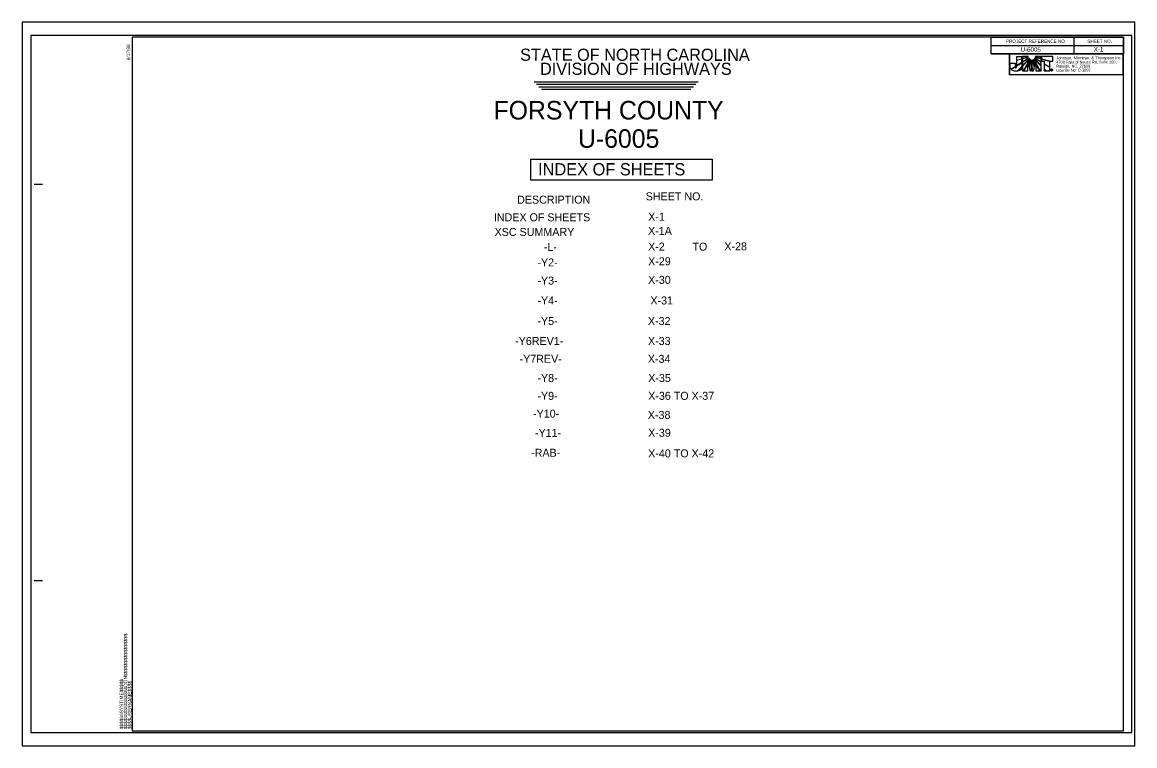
# Model space of a CAD drawing. Extents: x 2221 to 2389, y -3371 to -3261.
import ezdxf

# ---------------------------------------------------------------- set-up
doc = ezdxf.new("R2010")
doc.units = 0
for name, color, linetype in [('Default', 7, 'Continuous'), ('Old_Level_12', 7, 'Continuous'), ('Old_Level_40', 7, 'Continuous'), ('Old_Level_44', 7, 'Continuous'), ('Prop PHM Black Shape', 7, 'Continuous'), ('Sheet Block Title CELL', 7, 'Continuous'), ('Sheet Data Field CELL', 7, 'Continuous'), ('Sheet Plan CELL', 7, 'Continuous'), ('Sheet Plot Border Inside CELL', 7, 'Continuous'), ('Sheet Plot Border Outside CELL', 7, 'Continuous')]:
    doc.layers.add(name, color=color, linetype=linetype)

msp = doc.modelspace()

# ---------------------------------------------------------------- linework, layer by layer
at = {"layer": 'Default'}
for p, q in [((2372.01, -3266.51), (2371.2, -3266.51)), ((2371.2, -3266.51), (2371.21, -3267.04)), ((2371.21, -3267.04), (2372.01, -3266.82)), ((2372.01, -3266.87), (2371.21, -3267.1)), ((2371.21, -3267.1), (2371.21, -3267.85)), ((2371.21, -3267.85), (2372.01, -3267.34)), ((2372.01, -3266.82), (2372.01, -3266.51)), ((2372.01, -3267.34), (2372.01, -3266.87)), ((2373, -3266.5), (2372.09, -3266.5)), ((2372.09, -3266.5), (2372.09, -3266.79)), ((2372.09, -3266.79), (2372.77, -3266.6)), ((2372.77, -3266.66), (2372.09, -3266.85)), ((2372.09, -3266.85), (2372.09, -3267.29)), ((2372.09, -3267.29), (2372.7, -3266.9)), ((2372.79, -3266.91), (2372.09, -3267.36)), ((2372.09, -3267.36), (2372.1, -3267.86)), ((2372.1, -3267.86), (2372.94, -3266.97)), ((2372.98, -3267.02), (2372.1, -3267.94)), ((2372.23, -3268.67), (2372.89, -3267.48)), ((2372.89, -3267.6), (2372.29, -3268.67)), ((2372.7, -3266.9), (2373.03, -3266.63)), ((2372.77, -3266.6), (2373, -3266.5)), ((2373.03, -3266.63), (2372.77, -3266.66)), ((2373.1, -3266.76), (2372.79, -3266.91)), ((2372.89, -3267.48), (2372.88, -3267.27)), ((2372.88, -3267.27), (2372.92, -3267.42)), ((2372.89, -3268.67), (2372.89, -3267.6)), ((2372.92, -3267.42), (2373.09, -3267.11)), ((2372.94, -3266.97), (2373.1, -3266.76)), ((2373.15, -3267.13), (2372.95, -3267.49)), ((2372.95, -3267.49), (2373.08, -3267.98)), ((2373.19, -3266.85), (2372.98, -3267.02)), ((2373.08, -3267.98), (2373.28, -3267.17)), ((2373.09, -3267.11), (2373.19, -3266.85)), ((2373.33, -3267.22), (2373.1, -3268.09)), ((2373.31, -3266.92), (2373.15, -3267.13)), ((2373.28, -3267.17), (2373.31, -3266.92)), ((2373.44, -3266.96), (2373.33, -3267.22)), ((2373.47, -3267.59), (2373.44, -3266.96)), ((2373.48, -3268.67), (2373.47, -3267.59)), ((2373.57, -3266.96), (2373.53, -3267.59)), ((2373.53, -3267.59), (2373.54, -3268.67)), ((2373.68, -3267.22), (2373.57, -3266.96)), ((2373.91, -3268.1), (2373.68, -3267.22)), ((2373.7, -3266.92), (2373.73, -3267.18)), ((2373.86, -3267.13), (2373.7, -3266.92)), ((2373.73, -3267.18), (2373.94, -3267.99)), ((2373.81, -3266.85), (2373.91, -3267.11)), ((2374.03, -3267.01), (2373.81, -3266.85)), ((2374.07, -3267.5), (2373.86, -3267.13)), ((2373.91, -3266.75), (2374.06, -3266.97)), ((2374.22, -3266.91), (2373.91, -3266.75)), ((2373.91, -3267.11), (2374.09, -3267.43)), ((2373.94, -3267.99), (2374.07, -3267.5)), ((2373.98, -3266.63), (2374.32, -3266.9)), ((2374.23, -3266.66), (2373.98, -3266.63)), ((2374.91, -3266.5), (2374.02, -3266.49)), ((2374.02, -3266.49), (2374.25, -3266.6)), ((2374.91, -3267.94), (2374.03, -3267.01)), ((2374.06, -3266.97), (2374.91, -3267.86)), ((2374.09, -3267.43), (2374.13, -3267.27)), ((2374.13, -3267.27), (2374.13, -3267.5)), ((2374.13, -3267.5), (2374.77, -3268.67)), ((2374.71, -3268.66), (2374.13, -3267.62)), ((2374.13, -3267.62), (2374.13, -3268.66)), ((2374.91, -3267.34), (2374.22, -3266.91)), ((2374.92, -3266.85), (2374.23, -3266.66)), ((2374.25, -3266.6), (2374.92, -3266.79)), ((2374.32, -3266.9), (2374.91, -3267.27)), ((2374.92, -3266.79), (2374.91, -3266.5)), ((2374.91, -3267.27), (2374.92, -3266.85)), ((2374.91, -3267.86), (2374.91, -3267.34)), ((2376.67, -3266.49), (2374.98, -3266.49)), ((2374.98, -3266.49), (2374.98, -3266.8)), ((2374.98, -3266.8), (2374.98, -3266.81)), ((2374.98, -3266.81), (2376.31, -3267.18)), ((2374.98, -3266.86), (2374.98, -3266.86)), ((2374.98, -3266.86), (2374.98, -3267.19)), ((2376.23, -3267.21), (2374.98, -3266.86)), ((2374.98, -3267.19), (2375.39, -3267.19)), ((2375.39, -3267.19), (2375.39, -3267.57)), ((2375.39, -3267.57), (2376.23, -3268.1)), ((2375.39, -3267.64), (2375.4, -3268.36)), ((2376.23, -3268.16), (2375.39, -3267.64)), ((2376.23, -3268.1), (2376.23, -3267.21)), ((2376.31, -3267.18), (2376.67, -3267.18)), ((2376.67, -3267.18), (2376.67, -3266.49)), ((2372.1, -3267.94), (2372.1, -3268.67)), ((2372.1, -3268.67), (2372.23, -3268.67)), ((2372.29, -3268.67), (2372.89, -3268.67)), ((2373.1, -3268.09), (2373.26, -3268.67)), ((2373.26, -3268.67), (2373.48, -3268.67)), ((2373.54, -3268.67), (2373.76, -3268.66)), ((2373.76, -3268.66), (2373.91, -3268.1)), ((2374.13, -3268.66), (2374.71, -3268.66)), ((2374.77, -3268.67), (2374.92, -3268.66)), ((2374.92, -3268.66), (2374.91, -3267.94)), ((2375.4, -3268.36), (2375.68, -3268.66)), ((2375.61, -3268.66), (2375.4, -3268.44)), ((2375.4, -3268.44), (2375.4, -3268.66)), ((2375.4, -3268.66), (2375.61, -3268.66)), ((2375.68, -3268.66), (2376.23, -3268.66)), ((2376.23, -3268.66), (2376.23, -3268.16)), ((2376.44, -3268.58), (2376.44, -3268.46)), ((2376.44, -3268.46), (2376.49, -3268.46)), ((2376.47, -3268.58), (2376.44, -3268.58)), ((2376.49, -3268.48), (2376.47, -3268.48)), ((2376.47, -3268.48), (2376.47, -3268.51)), ((2376.47, -3268.51), (2376.49, -3268.51)), ((2376.49, -3268.54), (2376.47, -3268.54)), ((2376.47, -3268.54), (2376.47, -3268.58)), ((2376.49, -3268.39), (2376.49, -3268.41)), ((2376.49, -3268.41), (2376.49, -3268.39)), ((2376.49, -3268.46), (2376.49, -3268.48)), ((2376.49, -3268.48), (2376.49, -3268.46)), ((2376.49, -3268.46), (2376.5, -3268.46)), ((2376.5, -3268.48), (2376.49, -3268.48)), ((2376.49, -3268.51), (2376.49, -3268.54)), ((2376.49, -3268.54), (2376.49, -3268.51)), ((2376.49, -3268.51), (2376.49, -3268.51)), ((2376.49, -3268.54), (2376.49, -3268.54)), ((2376.49, -3268.63), (2376.49, -3268.66)), ((2376.49, -3268.66), (2376.49, -3268.63)), ((2376.49, -3268.63), (2376.49, -3268.63)), ((2376.49, -3268.66), (2376.49, -3268.66))]:
    msp.add_line(p, q, dxfattribs=at)
for points in [[(2370.12, -3269.23), (2387.31, -3269.19), (2387.31, -3266.09), (2370.11, -3266.13)], [(2372.1, -3268.67), (2372.1, -3267.94), (2372.98, -3267.02), (2373.19, -3266.85), (2373.12, -3267.06), (2372.92, -3267.42), (2372.88, -3267.27), (2372.89, -3267.48), (2372.23, -3268.67)], [(2374.02, -3266.49), (2374.91, -3266.5), (2374.92, -3266.79), (2374.25, -3266.6)], [(2297.67, -3282.01), (2325.14, -3282.01), (2325.14, -3285.21), (2297.67, -3285.21)]]:
    msp.add_lwpolyline(points, close=True, dxfattribs=at)
for points in [[(2371.21, -3267.04), (2372.01, -3266.82), (2372.01, -3266.51), (2371.2, -3266.51), (2371.21, -3267.04)], [(2371.21, -3267.85), (2372.01, -3267.34), (2372.01, -3266.87), (2371.21, -3267.1), (2371.21, -3267.85)], [(2372.77, -3266.6), (2373, -3266.5), (2372.09, -3266.5), (2372.09, -3266.79), (2372.77, -3266.6)], [(2372.09, -3266.85), (2372.09, -3267.29), (2372.7, -3266.9), (2373.03, -3266.63), (2372.77, -3266.66), (2372.09, -3266.85)], [(2372.09, -3267.36), (2372.1, -3267.86), (2372.94, -3266.97), (2373.1, -3266.76), (2372.79, -3266.91), (2372.09, -3267.36)], [(2373.19, -3266.85), (2372.98, -3267.02), (2372.1, -3267.94), (2372.1, -3268.67), (2372.23, -3268.67), (2372.89, -3267.48), (2372.88, -3267.27), (2372.92, -3267.42), (2373.09, -3267.11), (2373.19, -3266.85)], [(2372.29, -3268.67), (2372.89, -3268.67), (2372.89, -3267.6), (2372.29, -3268.67)], [(2373.31, -3266.92), (2373.15, -3267.13), (2372.95, -3267.49), (2373.08, -3267.98), (2373.28, -3267.17), (2373.31, -3266.92)], [(2373.33, -3267.22), (2373.1, -3268.09), (2373.26, -3268.67), (2373.48, -3268.67), (2373.47, -3267.59), (2373.44, -3266.96), (2373.33, -3267.22)], [(2373.57, -3266.96), (2373.53, -3267.59), (2373.54, -3268.67), (2373.76, -3268.66), (2373.91, -3268.1), (2373.68, -3267.22), (2373.57, -3266.96)], [(2373.7, -3266.92), (2373.73, -3267.18), (2373.94, -3267.99), (2374.07, -3267.5), (2373.86, -3267.13), (2373.7, -3266.92)], [(2373.81, -3266.85), (2373.91, -3267.11), (2374.09, -3267.43), (2374.13, -3267.27), (2374.13, -3267.5), (2374.77, -3268.67), (2374.92, -3268.66), (2374.91, -3267.94), (2374.03, -3267.01), (2373.81, -3266.85)], [(2373.91, -3266.75), (2374.06, -3266.97), (2374.91, -3267.86), (2374.91, -3267.34), (2374.22, -3266.91), (2373.91, -3266.75)], [(2373.98, -3266.63), (2374.32, -3266.9), (2374.91, -3267.27), (2374.92, -3266.85), (2374.23, -3266.66), (2373.98, -3266.63)], [(2374.25, -3266.6), (2374.92, -3266.79), (2374.91, -3266.5), (2374.02, -3266.49), (2374.25, -3266.6)], [(2374.13, -3268.66), (2374.71, -3268.66), (2374.13, -3267.62), (2374.13, -3268.66)], [(2376.67, -3266.49), (2374.98, -3266.49), (2374.98, -3266.8), (2374.98, -3266.81), (2376.31, -3267.18), (2376.67, -3267.18), (2376.67, -3266.49)], [(2374.98, -3266.86), (2374.98, -3266.86), (2374.98, -3267.19), (2375.39, -3267.19), (2375.39, -3267.57), (2376.23, -3268.1), (2376.23, -3267.21), (2374.98, -3266.86)], [(2375.39, -3267.64), (2375.4, -3268.36), (2375.68, -3268.66), (2376.23, -3268.66), (2376.23, -3268.16), (2375.39, -3267.64), (2375.39, -3267.64)], [(2375.4, -3268.66), (2375.4, -3268.66), (2375.61, -3268.66), (2375.4, -3268.44), (2375.4, -3268.66)], [(2376.55, -3268.55), (2376.55, -3268.56), (2376.55, -3268.57), (2376.55, -3268.57), (2376.55, -3268.58), (2376.52, -3268.58)]]:
    msp.add_lwpolyline(points, dxfattribs=at)
for points, degree in [([(2370.98, -3267.51), (2370.98, -3267.51), (2370.23, -3267.51), (2370.23, -3267.51), (2370.23, -3267.51), (2370.23, -3267.98), (2370.23, -3267.98), (2370.23, -3267.98), (2370.23, -3268.03), (2370.23, -3268.03), (2370.23, -3268.17), (2370.28, -3268.29), (2370.37, -3268.38), (2370.37, -3268.38), (2370.98, -3268.01), (2370.98, -3268), (2370.98, -3268), (2370.98, -3267.51), (2370.98, -3267.51)], 3), ([(2371.09, -3268.18), (2371.05, -3268.18), (2371, -3268.15), (2370.99, -3268.06), (2370.99, -3268.06), (2370.41, -3268.42), (2370.41, -3268.42), (2370.59, -3268.61), (2370.87, -3268.72), (2371.11, -3268.72), (2371.18, -3268.72), (2371.22, -3268.71), (2371.29, -3268.7), (2371.29, -3268.7), (2372.01, -3267.95), (2372.01, -3267.95), (2372.01, -3267.95), (2372.01, -3267.41), (2372.01, -3267.41), (2372.01, -3267.41), (2371.21, -3267.92), (2371.21, -3267.92), (2371.21, -3268.12), (2371.16, -3268.18), (2371.09, -3268.18)], 3), ([(2371.09, -3268.18), (2371.05, -3268.18), (2371, -3268.15), (2370.99, -3268.06), (2370.99, -3268.06), (2370.41, -3268.42), (2370.41, -3268.42), (2370.59, -3268.61), (2370.87, -3268.72), (2371.11, -3268.72), (2371.18, -3268.72), (2371.22, -3268.71), (2371.29, -3268.7), (2371.29, -3268.7), (2372.01, -3267.95), (2372.01, -3267.95), (2372.01, -3267.95), (2372.01, -3267.41), (2372.01, -3267.41), (2372.01, -3267.41), (2371.21, -3267.92), (2371.21, -3267.92), (2371.21, -3268.12), (2371.16, -3268.18), (2371.09, -3268.18)], 3), ([(2372.01, -3268.03), (2372.01, -3268.03), (2371.39, -3268.68), (2371.39, -3268.68), (2371.7, -3268.61), (2372, -3268.4), (2372.01, -3268.03)], 3), ([(2376.49, -3268.66), (2376.46, -3268.66), (2376.42, -3268.65), (2376.4, -3268.62), (2376.37, -3268.59), (2376.36, -3268.56), (2376.36, -3268.52), (2376.36, -3268.48), (2376.37, -3268.45), (2376.4, -3268.43), (2376.42, -3268.4), (2376.45, -3268.39), (2376.49, -3268.39)], 3), ([(2376.49, -3268.41), (2376.46, -3268.41), (2376.44, -3268.42), (2376.41, -3268.44), (2376.39, -3268.47), (2376.38, -3268.49), (2376.38, -3268.52), (2376.38, -3268.55), (2376.39, -3268.58), (2376.42, -3268.6), (2376.44, -3268.62), (2376.46, -3268.63), (2376.49, -3268.63)], 3), ([(2376.49, -3268.39), (2376.53, -3268.39), (2376.56, -3268.4), (2376.59, -3268.43), (2376.62, -3268.45), (2376.63, -3268.48), (2376.63, -3268.52)], 3), ([(2376.49, -3268.63), (2376.52, -3268.63), (2376.55, -3268.62), (2376.57, -3268.6), (2376.59, -3268.58), (2376.6, -3268.55), (2376.6, -3268.52), (2376.6, -3268.49), (2376.59, -3268.46), (2376.57, -3268.44), (2376.55, -3268.42), (2376.52, -3268.41), (2376.49, -3268.41)], 3), ([(2376.49, -3268.51), (2376.51, -3268.51), (2376.52, -3268.51), (2376.52, -3268.5), (2376.52, -3268.49), (2376.51, -3268.48), (2376.5, -3268.48)], 3), ([(2376.63, -3268.52), (2376.63, -3268.56), (2376.62, -3268.59), (2376.59, -3268.62), (2376.56, -3268.64), (2376.53, -3268.66), (2376.49, -3268.66)], 3), ([(2376.51, -3268.54), (2376.51, -3268.54), (2376.5, -3268.54), (2376.49, -3268.54)], 2), ([(2376.5, -3268.46), (2376.53, -3268.46), (2376.55, -3268.47), (2376.55, -3268.5), (2376.55, -3268.51), (2376.54, -3268.52), (2376.53, -3268.52)], 3), ([(2376.52, -3268.58), (2376.52, -3268.58), (2376.52, -3268.57), (2376.52, -3268.56), (2376.52, -3268.55), (2376.52, -3268.54), (2376.51, -3268.54)], 3), ([(2376.53, -3268.52), (2376.54, -3268.53), (2376.54, -3268.54), (2376.55, -3268.55)], 2)]:
    msp.add_open_spline(points, degree=degree, dxfattribs=at)
at = {"layer": 'Old_Level_12'}
for p, q in [((2298.2, -3270.29), (2323.04, -3270.3)), ((2298.2, -3270.3), (2323.04, -3270.3)), ((2298.55, -3270.68), (2322.65, -3270.68)), ((2298.93, -3271.05), (2322.29, -3271.05)), ((2299.3, -3271.42), (2321.9, -3271.42))]:
    msp.add_line(p, q, dxfattribs=at)
at = {"layer": 'Prop PHM Black Shape'}
msp.add_lwpolyline([(2370.11, -3266.13), (2387.31, -3266.09), (2387.31, -3269.19), (2370.12, -3269.23)], close=True, dxfattribs=at)
at = {"layer": 'Sheet Block Title CELL'}
for p, q in [((2379.88, -3263.55), (2379.88, -3266.05)), ((2367.38, -3264.8), (2387.38, -3264.8)), ((2367.38, -3266.05), (2387.38, -3266.05))]:
    msp.add_line(p, q, dxfattribs=at)
msp.add_lwpolyline([(2367.38, -3263.54), (2387.38, -3263.54), (2387.38, -3266.05), (2367.38, -3266.05)], close=True, dxfattribs=at)
at = {"layer": 'Sheet Plan CELL'}
for p, q in [((2237.38, -3263.54), (2237.38, -3263.54)), ((2222.53, -3285.79), (2223.78, -3285.79)), ((2222.53, -3345.8), (2223.78, -3345.8)), ((2237.38, -3368.55), (2237.38, -3368.55))]:
    msp.add_line(p, q, dxfattribs=at)
msp.add_lwpolyline([(2387.38, -3263.54), (2237.38, -3263.54), (2237.38, -3368.55), (2387.38, -3368.55)], close=True, dxfattribs=at)
at = {"layer": 'Sheet Plot Border Inside CELL'}
msp.add_lwpolyline([(2222.03, -3368.8), (2388.63, -3368.8), (2388.63, -3263.29), (2222.03, -3263.29)], close=True, dxfattribs=at)
at = {"layer": 'Sheet Plot Border Outside CELL'}
msp.add_lwpolyline([(2220.73, -3370.8), (2389.08, -3370.8), (2389.08, -3261.29), (2220.73, -3261.29)], close=True, dxfattribs=at)

# ---------------------------------------------------------------- texts
at = {"layer": 'Default'}
for s, height, rotation, p in [('Johnson, Mirmiran, & Thompson Inc.', 0.4392, 0.1414, (2377.2, -3266.91)), ('4700 Falls of Neuse Rd, Suite 100, ', 0.4267, 0.1414, (2377.2, -3267.55)), ('Raleigh, NC, 27609', 0.4267, 0.1414, (2377.2, -3268.16)), ('License No: C-3097', 0.4267, 0.1414, (2377.2, -3268.77)), ('INDEX OF SHEETS', 1.8509, 359.992, (2298.79, -3284.47)), ('DESCRIPTION', 1.2112, 359.992, (2295.62, -3288.75)), ('SHEET NO.', 1.211, 359.992, (2315.08, -3288.25))]:
    msp.add_text(s, height=height, rotation=rotation, dxfattribs=at).set_placement(p)
for s, height, p in [('INDEX OF SHEETS ', 1.2112, (2292.1, -3291.42)), ('X-1', 1.211, (2315.45, -3291.34)), ('XSC SUMMARY', 1.2112, (2292.21, -3293.64)), ('X-1A', 1.211, (2315.43, -3293.47)), ('X-2', 1.211, (2315.44, -3295.85)), ('TO', 1.211, (2322.15, -3295.86)), ('X-28', 1.211, (2326.98, -3295.82)), ('-L-', 1.211, (2299.67, -3295.92)), ('-Y2-', 1.211, (2298.69, -3298.25)), ('X-29', 1.211, (2315.44, -3298.08)), ('X-30', 1.211, (2315.44, -3300.89)), ('-Y3-', 1.211, (2298.69, -3301)), ('-Y4-', 1.211, (2298.69, -3304.01)), ('X-31', 1.211, (2315.79, -3304.01)), ('-Y5-', 1.211, (2298.69, -3307.12)), ('X-32', 1.211, (2315.41, -3307.12)), ('-Y6REV1-', 1.211, (2295.32, -3310.14)), ('X-33', 1.211, (2315.42, -3310.14)), ('-Y7REV-', 1.211, (2295.99, -3312.84)), ('X-34', 1.211, (2315.4, -3312.84)), ('-Y8-', 1.211, (2298.69, -3315.74)), ('X-35', 1.211, (2315.46, -3315.74)), ('-Y9-', 1.211, (2298.69, -3318.44)), ('X-36 TO X-37', 1.2112, (2315.45, -3318.44)), ('-Y10-', 1.211, (2298.03, -3321.14)), ('X-38', 1.211, (2315.4, -3321.33)), ('-Y11-', 1.211, (2298.32, -3324.05)), ('X-39', 1.211, (2315.45, -3324.03)), ('-RAB-', 1.211, (2297.74, -3327.06)), ('X-40 TO X-42', 1.2112, (2315.45, -3327.15))]:
    msp.add_text(s, height=height, dxfattribs=at).set_placement(p)
at = {"layer": 'Old_Level_40'}
for s, height, p in [('FORSYTH COUNTY', 2.8069, (2292.05, -3276.01)), ('U-6005', 2.807, (2304.83, -3280.3))]:
    msp.add_text(s, height=height, rotation=359.9982, dxfattribs=at).set_placement(p)
at = {"layer": 'Old_Level_44'}
for s, p in [('STATE OF NORTH CAROLINA', (2296.07, -3267.13)), ('DIVISION OF HIGHWAYS', (2299.08, -3269.26))]:
    msp.add_text(s, height=1.8416, rotation=359.9915, dxfattribs=at).set_placement(p)
at = {"layer": 'Sheet Block Title CELL'}
for s, p in [('PROJECT REFERENCE NO.', (2369.6, -3264.41)), ('SHEET NO.', (2381.91, -3264.42))]:
    msp.add_text(s, height=0.5, dxfattribs=at).set_placement(p)
at = {"layer": 'Sheet Data Field CELL'}
for s, p in [('U-6005', (2371.81, -3265.76)), ('X-1', (2382.88, -3265.73))]:
    msp.add_text(s, height=0.675, dxfattribs=at).set_placement(p)
at = {"layer": 'Sheet Plan CELL'}
for s, p in [('8/17/99', (2237.06, -3267.06)), ('$$$$$$$$$$$$$$$$DGN$$$$$$$$$$$$$$$$', (2236.62, -3368.31)), ('$$$$$$SYSTIME$$$$$', (2236.01, -3368.31)), ('$$$$USERNAME$$$$', (2237.27, -3368.31))]:
    msp.add_text(s, height=0.525, rotation=90, dxfattribs=at).set_placement(p)

doc.saveas('drawing.dxf')
